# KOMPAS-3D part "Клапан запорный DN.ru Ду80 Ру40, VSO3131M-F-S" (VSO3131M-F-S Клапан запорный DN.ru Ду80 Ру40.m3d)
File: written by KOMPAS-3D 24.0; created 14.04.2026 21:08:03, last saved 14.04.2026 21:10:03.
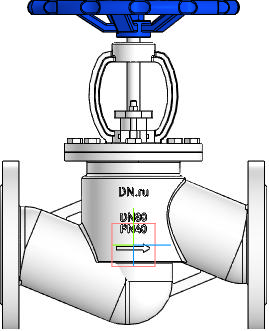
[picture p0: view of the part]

Document properties: Автор: R2D2; Полное имя файла: E:\Работа\Зайцев\VSO3131M-F-S Клапан запорный DN.ru Ду15-100 Ру40\DN80\VSO3131M-F-S Клапан запорный DN.ru Ду80 Ру40.m3d

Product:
- Part/product: Клапан запорный DN.ru Ду80 Ру40  | designation VSO3131M-F-S
    Масса: 22.29
    Раздел спецификации: Прочие изделия
    Примечание: D090-02144

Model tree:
1. Операция без истории:2

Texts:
  VSO3131M-F-S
